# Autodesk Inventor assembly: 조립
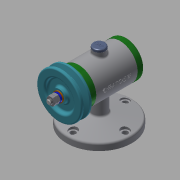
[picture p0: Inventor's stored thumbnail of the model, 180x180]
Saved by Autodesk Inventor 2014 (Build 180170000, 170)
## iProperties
Created: 2018-12
Part Number: 조립
Document SubType Name: Assembly
Designer: kh
Author: kh
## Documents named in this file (15)
- C:\Users\kh\Desktop\481207V1021\481207V1021\조립.iam
- C:\Users\kh\Desktop\481207V1021\481207V1021\본체.ipt
- C:\Users\kh\Desktop\481207V1021\481207V1021\V벨트풀리.ipt
- C:\Users\kh\Desktop\481207V1021\481207V1021\고무캡.ipt
- C:\Users\kh\Desktop\481207V1021\481207V1021\너트 M8.ipt
- 너트 M8.ipt
- C:\Users\kh\Desktop\481207V1021\481207V1021\뒤커버.ipt
- C:\Users\kh\Desktop\481207V1021\481207V1021\베어링 15 x 32 x 9.ipt
- C:\Users\kh\Desktop\481207V1021\481207V1021\볼트 M4 x 12.ipt
- C:\Users\kh\Desktop\481207V1021\481207V1021\스프링와셔 8.ipt
- C:\Users\kh\Desktop\481207V1021\481207V1021\앞커버.ipt
- C:\Users\kh\Desktop\481207V1021\481207V1021\오일 실 15 25 7.ipt
- C:\Users\kh\Desktop\481207V1021\481207V1021\와셔 8x17.ipt
- C:\Users\kh\Desktop\481207V1021\481207V1021\축.ipt
- C:\Users\kh\Desktop\481207V1021\481207V1021\키 3 x 3 x 12.ipt
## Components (2 placed, 2 different names)
1. V벨트풀리:1 — Insert:13, Mate:2, Insert:14
2. 고무캡:1 — Insert:12
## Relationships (4: Insert 3, Mate 1)
- Insert:12: 고무캡:1
- Insert:13: V벨트풀리:1
- Mate:2: V벨트풀리:1
- Insert:14: V벨트풀리:1
